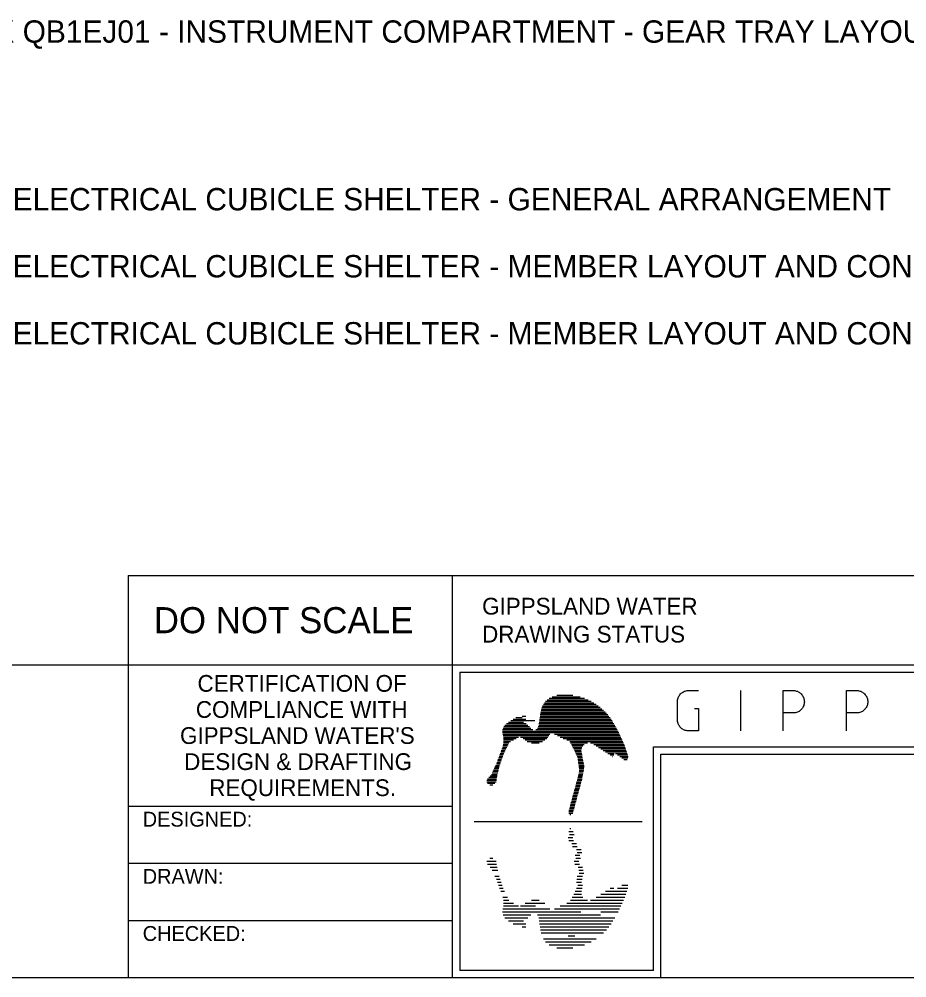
# Model space of a CAD drawing. Extents: x 0 to 841, y 0 to 594.
# Drawn here: x 577.9 to 697, y 15 to 143.7 of the extents above; entities that cross this region are included whole.
import ezdxf

# ---------------------------------------------------------------- set-up
doc = ezdxf.new("R2010")
doc.units = 0
doc.layers.add('A1BORDER', color=7, linetype='Continuous')
doc.layers.add('Level 1', color=7, linetype='Continuous')

msp = doc.modelspace()

# ---------------------------------------------------------------- linework, layer by layer
at = {"layer": 'A1BORDER'}
for p, q in [((592.5, 69), (592.5, 15)), ((592.5, 69), (829, 69)), ((636, 69), (636, 15)), ((28, 57), (829, 57)), ((637, 56), (788, 56)), ((637, 56), (637, 16)), ((650.01, 52.92), (652.2, 52.92)), ((648.12, 51.52), (655.59, 51.52)), ((648.23, 51.72), (655.31, 51.72)), ((648.37, 51.92), (655, 51.92)), ((648.53, 52.12), (654.64, 52.12)), ((648.74, 52.32), (654.24, 52.32)), ((649.02, 52.52), (653.76, 52.52)), ((649.39, 52.72), (653.15, 52.72)), ((647.81, 50.32), (656.86, 50.32)), ((647.85, 50.52), (656.69, 50.52)), ((647.88, 50.72), (656.5, 50.72)), ((647.91, 50.92), (656.3, 50.92)), ((647.96, 51.12), (656.08, 51.12)), ((648.03, 51.32), (655.85, 51.32)), ((643.04, 48.92), (646.16, 48.92)), ((643.26, 49.12), (645.9, 49.12)), ((643.54, 49.32), (645.57, 49.32)), ((643.85, 49.52), (647.09, 49.52)), ((644.18, 49.72), (645.89, 49.72)), ((644.54, 49.92), (645.36, 49.92)), ((645.37, 50.12), (645.86, 50.12)), ((647.61, 48.92), (657.8, 48.92)), ((647.63, 49.12), (657.68, 49.12)), ((647.66, 49.32), (657.57, 49.32)), ((647.69, 49.52), (657.44, 49.52)), ((647.71, 49.72), (657.31, 49.72)), ((647.75, 49.92), (657.17, 49.92)), ((647.78, 50.12), (657.02, 50.12)), ((642.73, 48.12), (658.25, 48.12)), ((642.74, 47.92), (658.35, 47.92)), ((642.75, 48.32), (646.79, 48.32)), ((642.79, 47.72), (649.08, 47.72)), ((642.81, 48.52), (646.55, 48.52)), ((642.9, 48.72), (646.37, 48.72)), ((647.19, 48.32), (658.14, 48.32)), ((647.42, 48.52), (658.03, 48.52)), ((647.54, 48.72), (657.92, 48.72)), ((649.72, 47.72), (658.45, 47.72)), ((642.83, 47.52), (648.95, 47.52)), ((642.84, 46.32), (643.5, 46.32)), ((642.85, 47.31), (644.88, 47.31)), ((642.87, 47.12), (644.57, 47.12)), ((642.87, 46.52), (643.6, 46.52)), ((642.88, 46.92), (644.23, 46.92)), ((642.88, 46.72), (643.83, 46.72)), ((645.14, 47.31), (648.83, 47.31)), ((645.49, 47.12), (648.67, 47.12)), ((645.76, 46.92), (648.42, 46.92)), ((646.05, 46.72), (648.11, 46.72)), ((646.62, 46.52), (647.67, 46.52)), ((650.12, 47.52), (658.55, 47.52)), ((650.48, 47.31), (658.64, 47.31)), ((650.87, 47.12), (658.73, 47.12)), ((651.36, 46.92), (658.82, 46.92)), ((651.76, 46.72), (658.9, 46.72)), ((651.88, 46.52), (654.15, 46.52)), ((651.99, 46.32), (653.71, 46.32)), ((654.57, 46.52), (658.99, 46.52)), ((655, 46.32), (659.07, 46.32)), ((642.43, 45.12), (642.9, 45.12)), ((642.5, 45.32), (643, 45.32)), ((642.57, 45.52), (643.1, 45.52)), ((642.65, 45.72), (643.2, 45.72)), ((642.72, 45.92), (643.3, 45.92)), ((642.79, 46.12), (643.4, 46.12)), ((652.1, 46.12), (653.52, 46.12)), ((652.2, 45.92), (653.4, 45.92)), ((652.31, 45.72), (653.33, 45.72)), ((652.41, 45.52), (653.31, 45.52)), ((652.5, 45.32), (653.34, 45.32)), ((652.6, 45.12), (653.38, 45.12)), ((655.31, 46.12), (659.14, 46.12)), ((655.62, 45.92), (659.22, 45.92)), ((655.93, 45.72), (659.29, 45.72)), ((656.24, 45.52), (659.35, 45.52)), ((656.55, 45.32), (659.42, 45.32)), ((656.86, 45.12), (657.74, 45.12)), ((657.91, 45.12), (659.48, 45.12)), ((663, 46), (788, 46)), ((663, 16), (663, 46)), ((641.99, 43.92), (642.48, 43.92)), ((642.06, 44.12), (642.55, 44.12)), ((642.13, 44.32), (642.62, 44.32)), ((642.21, 44.52), (642.69, 44.52)), ((642.28, 44.72), (642.76, 44.72)), ((642.35, 44.92), (642.83, 44.92)), ((652.69, 44.92), (653.41, 44.92)), ((652.78, 44.72), (653.44, 44.72)), ((652.83, 44.52), (653.48, 44.52)), ((652.86, 44.32), (653.53, 44.32)), ((652.89, 44.12), (653.57, 44.12)), ((652.91, 43.92), (653.62, 43.92)), ((657.17, 44.92), (657.68, 44.92)), ((657.51, 44.72), (657.54, 44.72)), ((658.19, 44.92), (659.54, 44.92)), ((658.47, 44.72), (659.59, 44.72)), ((658.75, 44.52), (659.58, 44.52)), ((659.02, 44.32), (659.47, 44.32)), ((664, 45), (829, 45)), ((664, 15), (664, 45)), ((641.37, 42.52), (642.09, 42.52)), ((641.46, 42.72), (642.15, 42.72)), ((641.55, 42.92), (642.2, 42.92)), ((641.64, 43.12), (642.25, 43.12)), ((641.73, 43.32), (642.3, 43.32)), ((641.82, 43.51), (642.35, 43.51)), ((641.91, 43.72), (642.41, 43.72)), ((652.94, 43.72), (653.67, 43.72)), ((652.97, 43.51), (653.71, 43.51)), ((652.99, 42.52), (653.57, 42.52)), ((653, 43.32), (653.69, 43.32)), ((653.02, 43.12), (653.67, 43.12)), ((653.03, 42.72), (653.61, 42.72)), ((653.05, 42.92), (653.64, 42.92)), ((640.62, 41.32), (641.88, 41.32)), ((640.63, 41.52), (641.93, 41.52)), ((640.73, 41.72), (641.95, 41.72)), ((640.9, 41.92), (641.97, 41.92)), ((641.1, 42.12), (642, 42.12)), ((641.25, 42.31), (642.04, 42.31)), ((652.68, 41.32), (653.31, 41.32)), ((652.74, 41.52), (653.37, 41.52)), ((652.79, 41.72), (653.41, 41.72)), ((652.85, 41.92), (653.45, 41.92)), ((652.9, 42.12), (653.49, 42.12)), ((652.95, 42.31), (653.53, 42.31)), ((640.72, 41.12), (641.73, 41.12)), ((641.03, 40.92), (641.43, 40.92)), ((652.3, 39.92), (652.93, 39.92)), ((652.36, 40.12), (652.99, 40.12)), ((652.41, 40.32), (653.04, 40.32)), ((652.47, 40.52), (653.1, 40.52)), ((652.52, 40.72), (653.15, 40.72)), ((652.57, 40.92), (653.2, 40.92)), ((652.63, 41.12), (653.26, 41.12)), ((651.98, 38.72), (652.61, 38.72)), ((652.03, 38.92), (652.66, 38.92)), ((652.09, 39.12), (652.72, 39.12)), ((652.14, 39.32), (652.77, 39.32)), ((652.2, 39.52), (652.82, 39.52)), ((652.25, 39.72), (652.88, 39.72)), ((636, 38), (592.5, 38)), ((651.63, 37.32), (652.23, 37.32)), ((651.65, 37.52), (652.28, 37.52)), ((651.71, 37.72), (652.34, 37.72)), ((651.76, 37.92), (652.39, 37.92)), ((651.82, 38.12), (652.44, 38.12)), ((651.87, 38.32), (652.5, 38.32)), ((651.92, 38.52), (652.55, 38.52)), ((651.64, 37.12), (652.17, 37.12)), ((651.79, 36.92), (651.9, 36.92)), ((638.93, 35.98), (661.47, 35.98)), ((651.79, 35.04), (651.9, 35.04)), ((651.54, 33.84), (652.17, 33.84)), ((651.63, 34.64), (652.23, 34.64)), ((651.71, 34.24), (652.34, 34.24)), ((651.65, 33.44), (652.28, 33.44)), ((652.03, 33.04), (652.66, 33.04)), ((652.14, 32.64), (652.77, 32.64)), ((652.66, 32.24), (653.29, 32.24)), ((641.03, 31.04), (641.43, 31.04)), ((652.47, 31.44), (653.1, 31.44)), ((652.57, 31.04), (653.2, 31.04)), ((652.77, 31.84), (653.4, 31.84)), ((636, 30.34), (592.5, 30.34)), ((640.62, 30.64), (641.88, 30.64)), ((640.73, 30.24), (641.95, 30.24)), ((641.1, 29.84), (642, 29.84)), ((652.34, 30.64), (652.97, 30.64)), ((652.45, 30.24), (653.07, 30.24)), ((652.9, 29.84), (653.49, 29.84)), ((641.37, 29.44), (642.09, 29.44)), ((641.73, 28.64), (642.3, 28.64)), ((652.77, 28.64), (653.46, 28.64)), ((652.99, 29.44), (653.57, 29.44)), ((653.05, 29.04), (653.64, 29.04)), ((641.91, 28.24), (642.41, 28.24)), ((642.06, 27.84), (642.55, 27.84)), ((642.21, 27.44), (642.69, 27.44)), ((642.35, 27.04), (642.83, 27.04)), ((652.66, 27.84), (653.35, 27.84)), ((652.69, 27.04), (653.41, 27.04)), ((652.72, 28.24), (653.44, 28.24)), ((652.83, 27.44), (653.48, 27.44)), ((657.17, 27.04), (657.68, 27.04)), ((658.19, 27.04), (659.54, 27.04)), ((658.75, 27.44), (659.58, 27.44)), ((642.5, 26.64), (643, 26.64)), ((642.79, 25.84), (643.4, 25.84)), ((652.1, 25.84), (653.52, 25.84)), ((652.31, 26.24), (653.33, 26.24)), ((652.5, 26.64), (653.34, 26.64)), ((655.31, 25.84), (659.14, 25.84)), ((655.93, 26.24), (659.29, 26.24)), ((656.55, 26.64), (659.42, 26.64)), ((642.85, 24.65), (644.88, 24.65)), ((642.87, 25.44), (643.6, 25.44)), ((642.88, 25.04), (644.23, 25.04)), ((645.14, 24.65), (647.18, 24.65)), ((645.76, 25.04), (648.42, 25.04)), ((646.62, 25.44), (647.67, 25.44)), ((650.48, 24.65), (658.64, 24.65)), ((651.36, 25.04), (658.82, 25.04)), ((651.88, 25.44), (654.15, 25.44)), ((654.57, 25.44), (658.99, 25.44)), ((642.73, 23.84), (653.27, 23.84)), ((642.79, 24.24), (649.08, 24.24)), ((642.81, 23.44), (646.55, 23.44)), ((647.42, 23.44), (655.89, 23.44)), ((649.72, 24.24), (658.45, 24.24)), ((655.94, 23.84), (658.25, 23.84)), ((636, 22.67), (592.5, 22.67)), ((643.04, 23.04), (646.16, 23.04)), ((643.54, 22.64), (645.57, 22.64)), ((644.18, 22.24), (645.89, 22.24)), ((647.61, 23.04), (657.8, 23.04)), ((647.66, 22.64), (657.57, 22.64)), ((647.71, 22.24), (657.31, 22.24)), ((645.37, 21.84), (645.86, 21.84)), ((647.78, 21.84), (657.02, 21.84)), ((647.85, 21.44), (656.69, 21.44)), ((647.91, 21.04), (656.3, 21.04)), ((651.57, 20.64), (652.44, 20.64)), ((648.23, 20.24), (655.31, 20.24)), ((648.53, 19.84), (654.64, 19.84)), ((649.02, 19.44), (653.76, 19.44)), ((650.01, 19.04), (652.2, 19.04)), ((663, 16), (637, 16)), ((829, 15), (28, 15))]:
    msp.add_line(p, q, dxfattribs=at)
for points in [[(668.49, 51.15), (669.06, 51.15), (669.06, 48.16), (667.64, 48.16), (667.51, 48.16), (667.39, 48.18), (667.28, 48.21), (667.15, 48.25), (667.04, 48.3), (666.93, 48.36), (666.82, 48.43), (666.73, 48.51), (666.64, 48.6), (666.55, 48.7), (666.48, 48.8), (666.41, 48.91), (666.35, 49.02), (666.31, 49.14), (666.27, 49.27), (666.24, 49.39), (666.22, 49.52), (666.22, 49.66), (666.22, 52.05), (666.22, 52.18), (666.24, 52.31), (666.27, 52.43), (666.31, 52.56), (666.35, 52.67), (666.41, 52.79), (666.48, 52.9), (666.55, 53), (666.64, 53.1), (666.73, 53.19), (666.82, 53.27), (666.93, 53.34), (667.04, 53.4), (667.15, 53.45), (667.28, 53.49), (667.39, 53.52), (667.51, 53.54), (667.64, 53.54), (669.06, 53.54)], [(674.74, 48.16), (674.74, 53.54)], [(680.42, 48.16), (680.42, 53.54), (681.84, 53.54), (681.96, 53.54), (682.08, 53.52), (682.2, 53.49), (682.32, 53.45), (682.43, 53.4), (682.54, 53.34), (682.65, 53.27), (682.74, 53.19), (682.84, 53.1), (682.92, 53), (682.99, 52.9), (683.06, 52.79), (683.12, 52.67), (683.17, 52.56), (683.21, 52.43), (683.23, 52.31), (683.25, 52.18), (683.26, 52.05), (683.25, 51.91), (683.23, 51.78), (683.21, 51.66), (683.17, 51.53), (683.12, 51.42), (683.06, 51.3), (682.99, 51.19), (682.92, 51.09), (682.84, 50.99), (682.74, 50.9), (682.65, 50.82), (682.54, 50.75), (682.43, 50.69), (682.32, 50.64), (682.2, 50.6), (682.08, 50.57), (681.96, 50.55), (681.84, 50.55), (680.42, 50.55)], [(688.93, 48.16), (688.93, 53.54), (690.35, 53.54), (690.47, 53.54), (690.59, 53.52), (690.71, 53.49), (690.83, 53.45), (690.94, 53.4), (691.05, 53.34), (691.16, 53.27), (691.26, 53.19), (691.35, 53.1), (691.43, 53), (691.51, 52.9), (691.57, 52.79), (691.63, 52.67), (691.68, 52.56), (691.72, 52.43), (691.75, 52.31), (691.76, 52.18), (691.77, 52.05), (691.76, 51.91), (691.75, 51.78), (691.72, 51.66), (691.68, 51.53), (691.63, 51.42), (691.57, 51.3), (691.51, 51.19), (691.43, 51.09), (691.35, 50.99), (691.26, 50.9), (691.16, 50.82), (691.05, 50.75), (690.94, 50.69), (690.83, 50.64), (690.71, 50.6), (690.59, 50.57), (690.47, 50.55), (690.35, 50.55), (688.93, 50.55)]]:
    msp.add_lwpolyline(points, dxfattribs=at)

# ---------------------------------------------------------------- texts
for s, height, p in [('GIPPSLAND WATER', 2.25, (640, 63.75)), ('DO NOT SCALE', 3.5, (595.922, 61.25)), ('DRAWING STATUS', 2.25, (640, 60)), ('CERTIFICATION OF', 2.25, (601.795, 53.39)), ('COMPLIANCE WITH', 2.25, (601.57, 49.89)), ("GIPPSLAND WATER'S", 2.25, (599.446, 46.39)), ('DESIGN & DRAFTING', 2.25, (600.004, 42.89)), ('REQUIREMENTS.', 2.25, (603.371, 39.39)), ('DESIGNED:', 2, (594.44, 35.29)), ('DRAWN:', 2, (594.44, 27.62)), ('CHECKED:', 2, (594.44, 19.95))]:
    msp.add_text(s, height=height, dxfattribs=at).set_placement(p)
at = {"layer": 'Level 1'}
for s, p in [('PUMP STATION 55kW TO 160kW (VSD) - JUNCTION BOX QB1EJ01 - INSTRUMENT COMPARTMENT - GEAR TRAY LAYOUT', (470, 140.5)), ('PUMP STATION 30kW TO 160kW (VSD) - CT METERED - ELECTRICAL CUBICLE SHELTER - GENERAL ARRANGEMENT', (470, 117.999)), ('PUMP STATION 30kW TO 160kW (VSD) - CT METERED - ELECTRICAL CUBICLE SHELTER - MEMBER LAYOUT AND CONNECTION DETAILS - SHEET 1 OF 2', (470, 109)), ('PUMP STATION 30kW TO 160kW (VSD) - CT METERED - ELECTRICAL CUBICLE SHELTER - MEMBER LAYOUT AND CONNECTION DETAILS - SHEET 2 OF 2', (470, 100))]:
    msp.add_text(s, height=3, dxfattribs=at).set_placement(p)

doc.saveas('drawing.dxf')
